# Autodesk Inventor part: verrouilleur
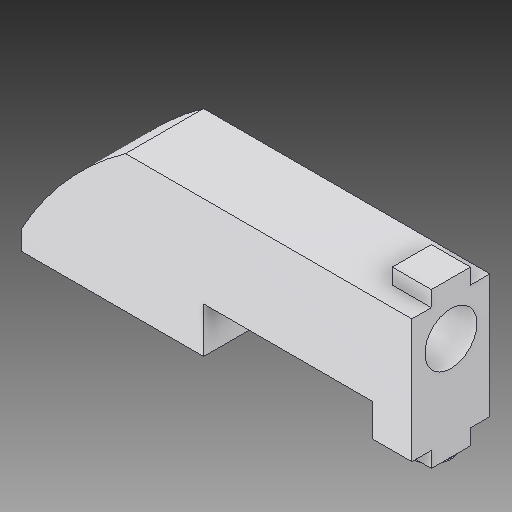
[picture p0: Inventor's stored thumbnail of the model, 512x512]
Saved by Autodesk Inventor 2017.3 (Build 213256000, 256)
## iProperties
Created: 2007-11
Part Number: verrouilleur
Material: solidworks materials|Alliage 7079|22
Document SubType Name: Modeling
Designer: ficho
Density: 2.7 g/cm^3
Appearance: 227,227,233
Author: ficho
Sending System: SolidWorks 2009
Last Author: christophe
Last Saved: 2011-01-23
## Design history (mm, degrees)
extrude "Extrusion4"
node "Solide1"
